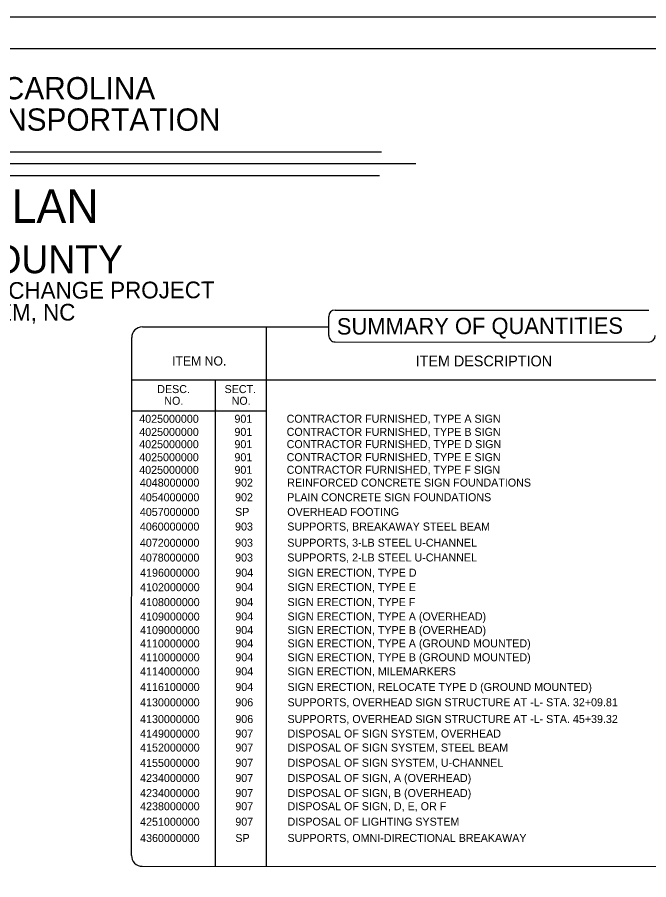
# Model space of a CAD drawing. Extents: x 49201 to 52602, y 49383 to 50479.
# Drawn here: x 51649 to 52173, y 49764 to 50479 of the extents above; entities that cross this region are included whole.
import ezdxf

# ---------------------------------------------------------------- set-up
doc = ezdxf.new("R2010")
doc.units = 0
for name, color, linetype in [('Default', 7, 'Continuous'), ('Old_Level_18', 7, 'Continuous'), ('Sheet Plot Border Outside CELL', 7, 'Continuous'), ('Sheet Title CELL', 7, 'Continuous')]:
    doc.layers.add(name, color=color, linetype=linetype)

msp = doc.modelspace()

# ---------------------------------------------------------------- linework, layer by layer
at = {"layer": 'Default'}
for p, q in [((51855.77, 49774.79), (51855.81, 50222.35)), ((51744.08, 50178.34), (52230.75, 50178.36)), ((51813.54, 49774.81), (51813.52, 50178.34)), ((51744.07, 50152.76), (51855.8, 50152.77)), ((51814.01, 50153.89), (51814.01, 50153.89))]:
    msp.add_line(p, q, dxfattribs=at)
for points in [[(51257.44, 50367.56), (51951.23, 50367.56)], [(51225.48, 50357.8), (51979.89, 50357.8)], [(51255.76, 50348.05), (51949.56, 50348.05)]]:
    msp.add_lwpolyline(points, dxfattribs=at)
at = {"layer": 'Old_Level_18'}
msp.add_lwpolyline([(52365.34, 50453.17), (50865.34, 50453.17), (50865.34, 49403.17), (52365.34, 49403.17)], close=True, dxfattribs=at)
at = {"layer": 'Sheet Plot Border Outside CELL'}
msp.add_lwpolyline([(52386.04, 50479.27), (50703.13, 50479.27), (50703.13, 49383.36), (52386.04, 49383.36)], close=True, dxfattribs=at)
at = {"layer": 'Sheet Title CELL'}
for p, q in [((51907.47, 50215.3), (51907.48, 50231.01)), ((51753.01, 50222.4), (51907.47, 50222.32)), ((51743.91, 49783.74), (51744.09, 50213.5)), ((51752.81, 49774.83), (52304.46, 49774.63))]:
    msp.add_line(p, q, dxfattribs=at)
for points in [[(51912.83, 50236.35), (52172.99, 50236.21)], [(51912.82, 50209.95), (52172.98, 50209.81)]]:
    msp.add_lwpolyline(points, dxfattribs=at)
for centre, radius, start, end in [((51912.82, 50231.01), 5.35, 89.97482, 179.97482), ((51753, 50213.49), 8.91, 89.97482, 179.97482), ((51912.82, 50215.3), 5.35, 179.97482, 269.97482), ((52172.98, 50215.15), 5.35, 269.97482, 359.97482), ((51752.82, 49783.74), 8.91, 179.97482, 269.97482)]:
    msp.add_arc(centre, radius, start, end, dxfattribs=at)

# ---------------------------------------------------------------- texts
at = {"layer": 'Default'}
for s, height, rotation, p in [('STATE OF NORTH CAROLINA', 18.4936, 360, (51414.58, 50411.15)), ('DEPARTMENT OF TRANSPORTATION', 18.4936, 360, (51371.15, 50385.12)), ('SIGNING PLAN', 27.7403, 360, (51452.71, 50308.68)), ('FORSYTH COUNTY', 23.1165, 360, (51449.94, 50266.86)), ('LOCATION: I-40 / NC 109 INTERCHANGE PROJECT', 13.8702, 0.18224, (51365.54, 50244.76)), ('IN WINSTON-SALEM, NC', 13.8702, 0.18224, (51479.94, 50226.94)), ('SUMMARY OF QUANTITIES', 13.5942, 0.15707, (51914.28, 50216.01)), ('ITEM NO.', 7.574, 0.00141, (51777.6, 50190.29)), ('ITEM DESCRIPTION', 8.91, 0.00141, (51979.61, 50189.62)), ('DESC.', 6.638, 0.00141, (51765.26, 50167.45)), ('SECT.', 6.638, 0.00141, (51821.12, 50167.45)), ('NO.', 6.638, 0.00141, (51771.13, 50157.74)), ('NO.', 6.638, 0.00141, (51826.99, 50157.74))]:
    msp.add_text(s, height=height, rotation=rotation, dxfattribs=at).set_placement(p)
for s, height, p in [('4025000000', 6.638, (51750.33, 50142.79)), ('901', 6.638, (51829.32, 50142.82)), ('CONTRACTOR FURNISHED, TYPE A SIGN', 6.6381, (51872.6, 50142.85)), ('4025000000', 6.638, (51750.33, 50131.89)), ('901', 6.638, (51829.32, 50131.93)), ('CONTRACTOR FURNISHED, TYPE B SIGN', 6.6381, (51872.6, 50131.95)), ('4025000000', 6.638, (51750.33, 50121.73)), ('901', 6.638, (51829.32, 50121.76)), ('CONTRACTOR FURNISHED, TYPE D SIGN', 6.6381, (51872.6, 50121.78)), ('4025000000', 6.638, (51750.33, 50110.91)), ('901', 6.638, (51829.32, 50110.94)), ('CONTRACTOR FURNISHED, TYPE E SIGN', 6.6381, (51872.6, 50110.96)), ('4025000000', 6.638, (51750.33, 50100.42)), ('901', 6.638, (51829.32, 50100.45)), ('CONTRACTOR FURNISHED, TYPE F SIGN', 6.6381, (51872.6, 50100.47)), ('4048000000', 6.638, (51750.85, 50089.81)), ('902', 6.638, (51829.84, 50089.85)), ('REINFORCED CONCRETE SIGN FOUNDATIONS', 6.6381, (51873.12, 50089.87)), ('PLAIN CONCRETE SIGN FOUNDATIONS', 6.6381, (51873.12, 50077.73)), ('4054000000', 6.638, (51750.85, 50077.67)), ('902', 6.638, (51829.84, 50077.71)), ('4057000000', 6.638, (51750.85, 50065.52)), ('SP', 6.638, (51829.84, 50065.56)), ('OVERHEAD FOOTING', 6.6381, (51873.12, 50065.58)), ('4060000000', 6.638, (51750.85, 50053.37)), ('903', 6.638, (51829.84, 50053.4)), ('SUPPORTS, BREAKAWAY STEEL BEAM', 6.6381, (51873.12, 50053.42)), ('4072000000', 6.638, (51750.87, 50039.93)), ('903', 6.638, (51829.87, 50039.97)), ('SUPPORTS, 3-LB STEEL U-CHANNEL', 6.6381, (51873.14, 50039.99)), ('4078000000', 6.638, (51750.87, 50027.66)), ('903', 6.638, (51829.87, 50027.7)), ('SUPPORTS, 2-LB STEEL U-CHANNEL', 6.6381, (51873.14, 50027.72)), ('4196000000', 6.638, (51751.06, 50015.07)), ('904', 6.638, (51830.05, 50015.11)), ('SIGN ERECTION, TYPE D', 6.6381, (51873.33, 50015.13)), ('4102000000', 6.638, (51751.06, 50003.08)), ('904', 6.638, (51830.05, 50003.12)), ('SIGN ERECTION, TYPE E', 6.6381, (51873.33, 50003.14)), ('4108000000', 6.638, (51751.06, 49990.7)), ('904', 6.638, (51830.05, 49990.73)), ('SIGN ERECTION, TYPE F', 6.6381, (51873.33, 49990.75)), ('4109000000', 6.638, (51751.06, 49978.74)), ('904', 6.638, (51830.05, 49978.78)), ('SIGN ERECTION, TYPE A (OVERHEAD)', 6.6381, (51873.33, 49978.8)), ('4109000000', 6.638, (51751.06, 49967.47)), ('904', 6.638, (51830.05, 49967.51)), ('SIGN ERECTION, TYPE B (OVERHEAD)', 6.6381, (51873.33, 49967.53)), ('4110000000', 6.638, (51751.06, 49956.42)), ('904', 6.638, (51830.05, 49956.46)), ('SIGN ERECTION, TYPE A (GROUND MOUNTED)', 6.6381, (51873.33, 49956.48)), ('4110000000', 6.638, (51751.06, 49944.92)), ('904', 6.638, (51830.05, 49944.95)), ('SIGN ERECTION, TYPE B (GROUND MOUNTED)', 6.6381, (51873.33, 49944.97)), ('4114000000', 6.638, (51751.06, 49933.21)), ('904', 6.638, (51830.05, 49933.25)), ('SIGN ERECTION, MILEMARKERS', 6.6381, (51873.33, 49933.27)), ('SIGN ERECTION, RELOCATE TYPE D (GROUND MOUNTED)', 6.6381, (51873.33, 49920.31)), ('4116100000', 6.638, (51751.06, 49920.25)), ('904', 6.638, (51830.05, 49920.29)), ('4130000000', 6.638, (51751.06, 49907.54)), ('906', 6.638, (51830.05, 49907.58)), ('SUPPORTS, OVERHEAD SIGN STRUCTURE AT -L- STA. 32+09.81', 6.6381, (51873.33, 49907.6)), ('4130000000', 6.638, (51751.06, 49893.65)), ('906', 6.638, (51830.05, 49893.69)), ('SUPPORTS, OVERHEAD SIGN STRUCTURE AT -L- STA. 45+39.32', 6.6381, (51873.33, 49893.71)), ('4149000000', 6.638, (51751.06, 49881.58)), ('907', 6.638, (51830.05, 49881.62)), ('DISPOSAL OF SIGN SYSTEM, OVERHEAD', 6.6381, (51873.33, 49881.64)), ('4152000000', 6.638, (51751.06, 49870)), ('907', 6.638, (51830.05, 49870.03)), ('DISPOSAL OF SIGN SYSTEM, STEEL BEAM', 6.6381, (51873.33, 49870.05)), ('4155000000', 6.638, (51751.06, 49857.33)), ('907', 6.638, (51830.05, 49857.37)), ('DISPOSAL OF SIGN SYSTEM, U-CHANNEL', 6.6381, (51873.33, 49857.39)), ('4234000000', 6.638, (51751.06, 49844.75)), ('907', 6.638, (51830.05, 49844.78)), ('DISPOSAL OF SIGN, A (OVERHEAD)', 6.6381, (51873.33, 49844.8)), ('4234000000', 6.638, (51751.06, 49832.25)), ('907', 6.638, (51830.05, 49832.28)), ('DISPOSAL OF SIGN, B (OVERHEAD)', 6.6381, (51873.33, 49832.3)), ('4238000000', 6.638, (51751.06, 49821.32)), ('907', 6.638, (51830.05, 49821.36)), ('DISPOSAL OF SIGN, D, E, OR F', 6.6381, (51873.33, 49821.38)), ('4251000000', 6.638, (51751.06, 49808.47)), ('907', 6.638, (51830.05, 49808.51)), ('DISPOSAL OF LIGHTING SYSTEM', 6.6381, (51873.33, 49808.53)), ('4360000000', 6.638, (51751.06, 49794.98)), ('SP', 6.638, (51830.05, 49795.01)), ('SUPPORTS, OMNI-DIRECTIONAL BREAKAWAY', 6.6381, (51873.33, 49795.03))]:
    msp.add_text(s, height=height, dxfattribs=at).set_placement(p)

doc.saveas('drawing.dxf')
